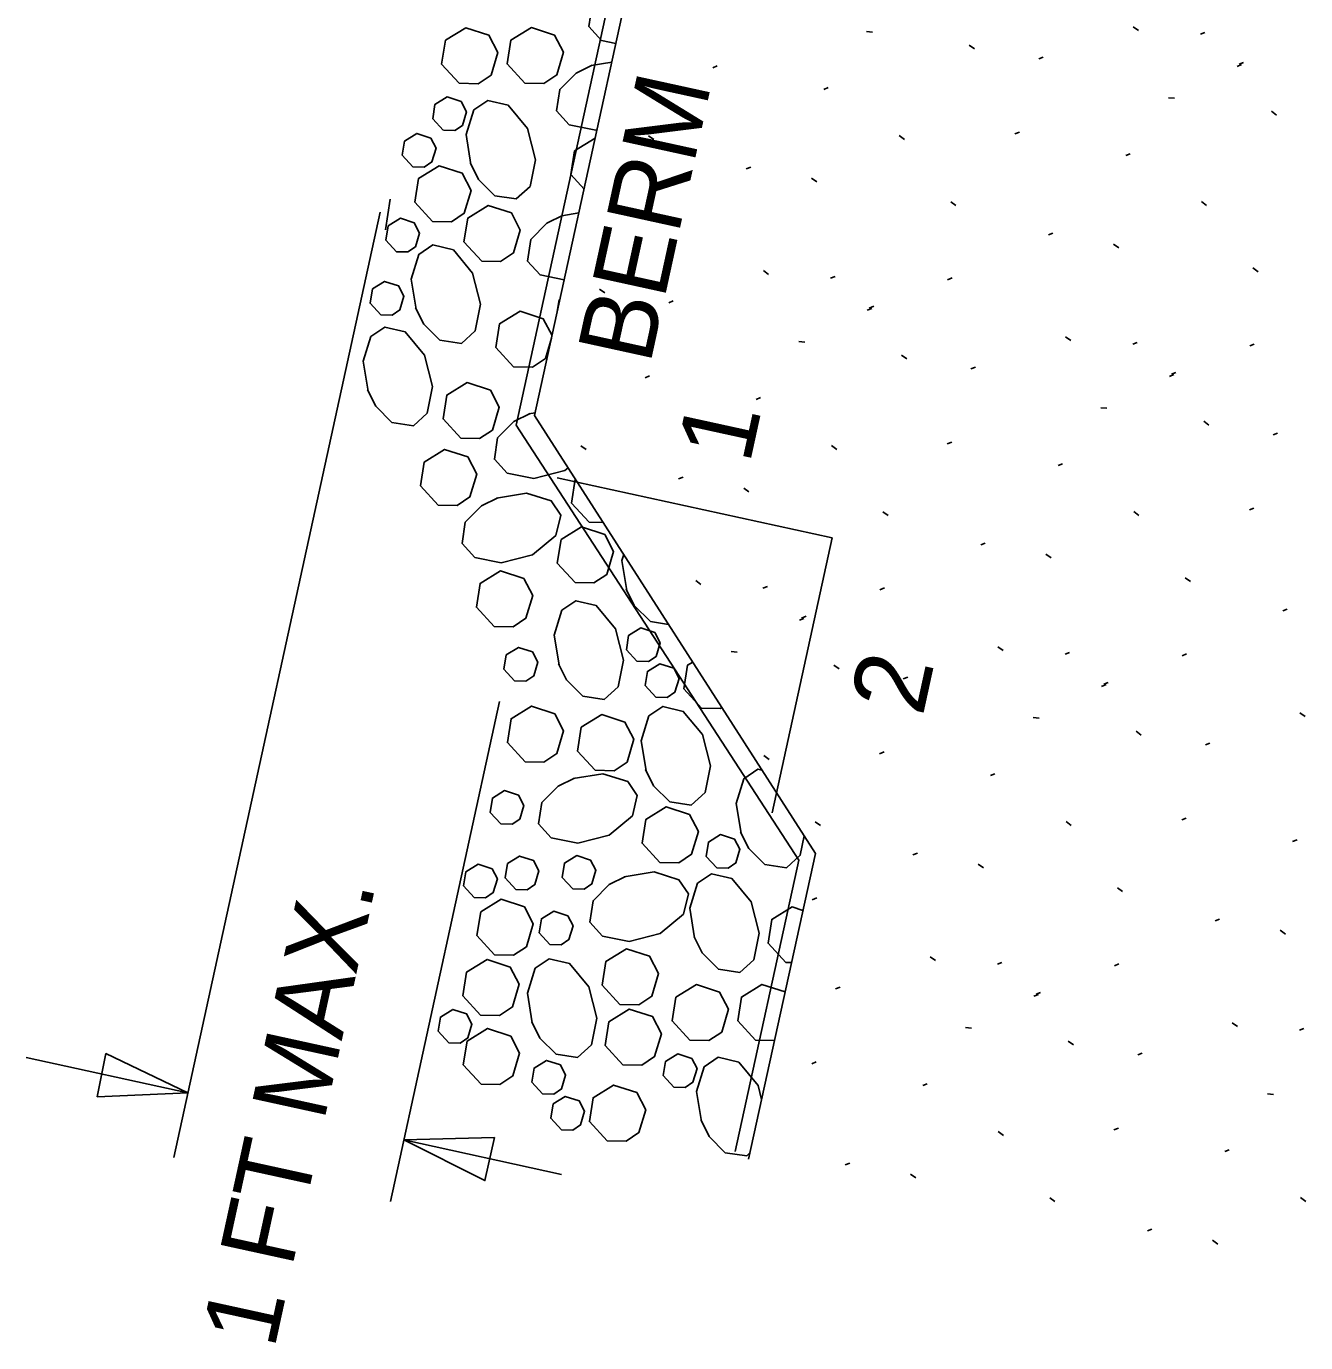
# Model space of a CAD drawing. Extents: x 2126110 to 2128246, y 1804858 to 1811658.
# Drawn here: x 2126703.9 to 2126789.7, y 1806267.7 to 1806355.9 of the extents above; entities that cross this region are included whole.
import ezdxf

# ---------------------------------------------------------------- set-up
doc = ezdxf.new("R2010")
doc.units = 0
doc.layers.add('1', color=7, linetype='Continuous')

msp = doc.modelspace()

# ---------------------------------------------------------------- linework, layer by layer
at = {"layer": '1'}
for p, q in [((2126736.789, 1806329.16), (2126742.894, 1806357.097)), ((2126743.847, 1806356.496), (2126738.017, 1806329.817)), ((2126760.279, 1806355.54), (2126760.679, 1806355.499)), ((2126778.519, 1806355.612), (2126778.167, 1806355.87)), ((2126782.676, 1806355.365), (2126782.974, 1806355.481)), ((2126767.524, 1806354.378), (2126767.172, 1806354.636)), ((2126771.826, 1806353.719), (2126772.124, 1806353.835)), ((2126741.803, 1806353.264), (2126743.191, 1806353.491)), ((2126749.974, 1806353.122), (2126750.272, 1806353.239)), ((2126785.13, 1806353.212), (2126785.429, 1806353.329)), ((2126785.267, 1806353.364), (2126785.566, 1806353.481)), ((2126757.41, 1806351.668), (2126757.708, 1806351.785)), ((2126780.541, 1806351.113), (2126780.941, 1806351.071)), ((2126787.787, 1806349.95), (2126787.434, 1806350.209)), ((2126746.013, 1806348.307), (2126745.66, 1806348.566)), ((2126762.83, 1806348.313), (2126762.477, 1806348.572)), ((2126770.236, 1806348.695), (2126770.534, 1806348.811)), ((2126777.673, 1806347.24), (2126777.971, 1806347.357)), ((2126752.213, 1806346.348), (2126752.511, 1806346.465)), ((2126756.936, 1806345.466), (2126756.583, 1806345.724)), ((2126728.01, 1806342.266), (2126728.334, 1806344.304)), ((2126766.275, 1806343.879), (2126765.923, 1806344.138)), ((2126783.092, 1806343.886), (2126782.74, 1806344.144)), ((2126727.665, 1806343.437), (2126713.821, 1806280.085)), ((2126739.853, 1806343.199), (2126740.982, 1806343.384)), ((2126745.459, 1806343.341), (2126745.757, 1806343.457)), ((2126772.475, 1806341.92), (2126772.774, 1806342.037)), ((2126777.198, 1806341.038), (2126776.846, 1806341.297)), ((2126753.716, 1806339.261), (2126753.364, 1806339.52)), ((2126786.538, 1806339.451), (2126786.185, 1806339.71)), ((2126757.873, 1806339.014), (2126758.171, 1806339.131)), ((2126765.721, 1806338.913), (2126766.019, 1806339.03)), ((2126742.721, 1806338.027), (2126742.369, 1806338.286)), ((2126747.023, 1806337.368), (2126747.321, 1806337.485)), ((2126760.327, 1806336.861), (2126760.626, 1806336.978)), ((2126760.464, 1806337.013), (2126760.763, 1806337.13)), ((2126773.979, 1806334.833), (2126773.627, 1806335.092)), ((2126755.738, 1806334.762), (2126756.138, 1806334.72)), ((2126778.135, 1806334.586), (2126778.434, 1806334.703)), ((2126785.984, 1806334.485), (2126786.282, 1806334.602)), ((2126762.984, 1806333.599), (2126762.631, 1806333.858)), ((2126745.433, 1806332.344), (2126745.731, 1806332.461)), ((2126767.285, 1806332.94), (2126767.583, 1806333.057)), ((2126780.59, 1806332.434), (2126780.888, 1806332.55)), ((2126780.727, 1806332.586), (2126781.025, 1806332.702)), ((2126752.87, 1806330.89), (2126753.168, 1806331.006)), ((2126737.637, 1806329.913), (2126738.053, 1806329.981)), ((2126738.017, 1806329.817), (2126756.848, 1806300.456)), ((2126776.001, 1806330.334), (2126776.401, 1806330.292)), ((2126755.732, 1806300.013), (2126736.789, 1806329.16)), ((2126783.246, 1806329.171), (2126782.894, 1806329.43)), ((2126765.696, 1806327.916), (2126765.994, 1806328.033)), ((2126787.548, 1806328.512), (2126787.846, 1806328.629)), ((2126741.472, 1806327.528), (2126741.12, 1806327.787)), ((2126758.289, 1806327.535), (2126757.937, 1806327.794)), ((2126773.132, 1806326.462), (2126773.431, 1806326.579)), ((2126739.525, 1806325.638), (2126757.976, 1806321.606)), ((2126747.672, 1806325.57), (2126747.971, 1806325.686)), ((2126752.395, 1806324.687), (2126752.043, 1806324.946)), ((2126785.958, 1806323.489), (2126786.257, 1806323.605)), ((2126761.735, 1806323.101), (2126761.382, 1806323.36)), ((2126778.552, 1806323.107), (2126778.2, 1806323.366)), ((2126742.626, 1806322.631), (2126741.674, 1806322.653)), ((2126757.976, 1806321.606), (2126753.947, 1806303.17)), ((2126767.935, 1806321.142), (2126768.233, 1806321.259)), ((2126772.658, 1806320.259), (2126772.305, 1806320.518)), ((2126749.176, 1806318.482), (2126748.823, 1806318.741)), ((2126753.332, 1806318.236), (2126753.631, 1806318.352)), ((2126781.997, 1806318.673), (2126781.645, 1806318.932)), ((2126761.181, 1806318.135), (2126761.479, 1806318.251)), ((2126788.197, 1806316.714), (2126788.496, 1806316.831)), ((2126755.787, 1806316.083), (2126756.085, 1806316.2)), ((2126755.924, 1806316.235), (2126756.222, 1806316.352)), ((2126751.198, 1806313.984), (2126751.598, 1806313.942)), ((2126769.439, 1806314.055), (2126769.086, 1806314.314)), ((2126773.595, 1806313.808), (2126773.893, 1806313.925)), ((2126758.443, 1806312.821), (2126758.091, 1806313.08)), ((2126781.443, 1806313.707), (2126781.742, 1806313.824)), ((2126762.745, 1806312.162), (2126763.043, 1806312.278)), ((2126776.05, 1806311.655), (2126776.348, 1806311.772)), ((2126776.186, 1806311.807), (2126776.485, 1806311.924)), ((2126735.667, 1806310.641), (2126728.343, 1806277.125)), ((2126771.46, 1806309.556), (2126771.86, 1806309.514)), ((2126789.701, 1806309.627), (2126789.349, 1806309.886)), ((2126778.706, 1806308.393), (2126778.353, 1806308.652)), ((2126783.007, 1806307.734), (2126783.306, 1806307.851)), ((2126753.749, 1806306.757), (2126753.396, 1806307.015)), ((2126761.155, 1806307.138), (2126761.454, 1806307.255)), ((2126768.592, 1806305.684), (2126768.89, 1806305.8)), ((2126757.194, 1806302.322), (2126756.842, 1806302.581)), ((2126774.012, 1806302.329), (2126773.659, 1806302.588)), ((2126781.418, 1806302.71), (2126781.716, 1806302.827)), ((2126788.854, 1806301.256), (2126789.153, 1806301.372)), ((2126751.464, 1806280.484), (2126755.732, 1806300.013)), ((2126752.372, 1806279.973), (2126756.848, 1806300.456)), ((2126763.394, 1806300.364), (2126763.693, 1806300.48)), ((2126768.117, 1806299.481), (2126767.765, 1806299.74)), ((2126777.457, 1806297.895), (2126777.104, 1806298.153)), ((2126756.64, 1806297.356), (2126756.938, 1806297.473)), ((2126783.657, 1806295.936), (2126783.955, 1806296.052)), ((2126788.38, 1806295.053), (2126788.027, 1806295.312)), ((2126755.249, 1806293.136), (2126754.861, 1806293.145)), ((2126764.898, 1806293.276), (2126764.546, 1806293.535)), ((2126769.054, 1806293.03), (2126769.353, 1806293.146)), ((2126776.903, 1806292.929), (2126777.201, 1806293.045)), ((2126758.204, 1806291.383), (2126758.503, 1806291.5)), ((2126771.509, 1806290.877), (2126771.807, 1806290.993)), ((2126771.646, 1806291.029), (2126771.944, 1806291.145)), ((2126766.92, 1806288.777), (2126767.32, 1806288.736)), ((2126785.161, 1806288.849), (2126784.808, 1806289.107)), ((2126789.317, 1806288.602), (2126789.615, 1806288.718)), ((2126774.165, 1806287.615), (2126773.813, 1806287.873)), ((2126703.927, 1806286.786), (2126714.768, 1806284.417)), ((2126778.467, 1806286.956), (2126778.765, 1806287.072)), ((2126756.615, 1806286.359), (2126756.913, 1806286.476)), ((2126764.051, 1806284.905), (2126764.35, 1806285.022)), ((2126787.183, 1806284.35), (2126787.582, 1806284.308)), ((2126729.246, 1806281.254), (2126739.819, 1806278.943)), ((2126769.471, 1806281.55), (2126769.119, 1806281.809)), ((2126776.877, 1806281.932), (2126777.176, 1806282.048)), ((2126784.314, 1806280.477), (2126784.612, 1806280.594)), ((2126758.854, 1806279.585), (2126759.152, 1806279.702)), ((2126763.577, 1806278.703), (2126763.224, 1806278.961)), ((2126772.916, 1806277.116), (2126772.564, 1806277.375)), ((2126789.734, 1806277.123), (2126789.381, 1806277.382)), ((2126779.117, 1806275.157), (2126779.415, 1806275.274)), ((2126783.839, 1806274.275), (2126783.487, 1806274.534))]:
    msp.add_line(p, q, dxfattribs=at)
for points in [[(2126743.466, 1806354.752), (2126742.507, 1806354.944), (2126741.661, 1806355.875), (2126741.876, 1806357.312), (2126742.965, 1806358.402), (2126744.058, 1806358.941)], [(2126732.965, 1806352.076), (2126731.778, 1806353.367), (2126732.033, 1806354.96), (2126733.405, 1806355.806), (2126734.959, 1806355.3), (2126735.555, 1806354.152), (2126735.103, 1806352.624), (2126734.235, 1806352.047), (2126732.965, 1806352.077)], [(2126737.363, 1806352.086), (2126736.176, 1806353.377), (2126736.431, 1806354.97), (2126737.803, 1806355.816), (2126739.357, 1806355.31), (2126739.953, 1806354.162), (2126739.501, 1806352.634), (2126738.633, 1806352.058), (2126737.363, 1806352.087)], [(2126742.201, 1806348.961), (2126742.122, 1806348.941), (2126740.337, 1806349.298), (2126739.491, 1806350.229), (2126739.706, 1806351.666), (2126740.795, 1806352.756), (2126741.887, 1806353.295)], [(2126731.896, 1806348.927), (2126731.184, 1806349.702), (2126731.336, 1806350.657), (2126732.161, 1806351.165), (2126733.092, 1806350.862), (2126733.45, 1806350.173), (2126733.179, 1806349.255), (2126732.658, 1806348.91), (2126731.897, 1806348.927)], [(2126733.748, 1806346.634), (2126733.42, 1806348.637), (2126733.936, 1806350.298), (2126734.877, 1806350.935), (2126736.245, 1806350.609), (2126737.539, 1806349.047), (2126738.07, 1806346.953), (2126737.713, 1806345.168), (2126736.783, 1806344.322), (2126735.345, 1806344.537), (2126734.256, 1806345.626), (2126733.717, 1806346.719)], [(2126729.851, 1806346.475), (2126729.14, 1806347.25), (2126729.292, 1806348.206), (2126730.116, 1806348.713), (2126731.048, 1806348.41), (2126731.406, 1806347.722), (2126731.134, 1806346.804), (2126730.614, 1806346.458), (2126729.852, 1806346.476)], [(2126741.333, 1806344.992), (2126740.448, 1806345.955), (2126740.702, 1806347.548), (2126742.075, 1806348.394), (2126742.077, 1806348.394)], [(2126731.166, 1806342.823), (2126729.98, 1806344.115), (2126730.233, 1806345.707), (2126731.607, 1806346.553), (2126733.16, 1806346.048), (2126733.756, 1806344.9), (2126733.304, 1806343.371), (2126732.436, 1806342.795), (2126731.166, 1806342.824)], [(2126734.469, 1806340.159), (2126733.282, 1806341.451), (2126733.536, 1806343.043), (2126734.909, 1806343.889), (2126736.463, 1806343.384), (2126737.059, 1806342.236), (2126736.607, 1806340.707), (2126735.738, 1806340.131), (2126734.469, 1806340.16)], [(2126728.749, 1806340.789), (2126728.037, 1806341.563), (2126728.189, 1806342.519), (2126729.014, 1806343.027), (2126729.945, 1806342.723), (2126730.303, 1806342.035), (2126730.032, 1806341.117), (2126729.511, 1806340.772), (2126728.75, 1806340.789)], [(2126740.004, 1806338.91), (2126738.387, 1806339.234), (2126737.542, 1806340.164), (2126737.757, 1806341.602), (2126738.846, 1806342.691), (2126739.938, 1806343.23)], [(2126730.07, 1806336.947), (2126729.742, 1806338.95), (2126730.258, 1806340.611), (2126731.199, 1806341.248), (2126732.567, 1806340.923), (2126733.862, 1806339.36), (2126734.393, 1806337.267), (2126734.035, 1806335.481), (2126733.105, 1806334.636), (2126731.668, 1806334.85), (2126730.578, 1806335.94), (2126730.039, 1806337.032)], [(2126727.696, 1806336.562), (2126726.984, 1806337.337), (2126727.136, 1806338.293), (2126727.96, 1806338.8), (2126728.892, 1806338.497), (2126729.25, 1806337.808), (2126728.979, 1806336.89), (2126728.457, 1806336.545), (2126727.696, 1806336.563)], [(2126739.511, 1806336.651), (2126739.656, 1806337.562), (2126739.718, 1806337.6)], [(2126736.604, 1806333.074), (2126735.418, 1806334.365), (2126735.672, 1806335.957), (2126737.045, 1806336.803), (2126738.599, 1806336.298), (2126739.186, 1806335.166)], [(2126726.85, 1806331.439), (2126726.522, 1806333.441), (2126727.038, 1806335.103), (2126727.979, 1806335.74), (2126729.347, 1806335.414), (2126730.642, 1806333.852), (2126731.173, 1806331.759), (2126730.815, 1806329.973), (2126729.885, 1806329.128), (2126728.448, 1806329.342), (2126727.358, 1806330.432), (2126726.819, 1806331.524)], [(2126739.149, 1806334.996), (2126738.743, 1806333.621), (2126737.874, 1806333.046), (2126736.605, 1806333.074)], [(2126733.061, 1806328.289), (2126731.876, 1806329.58), (2126732.129, 1806331.173), (2126733.502, 1806332.018), (2126735.056, 1806331.513), (2126735.652, 1806330.364), (2126735.2, 1806328.836), (2126734.332, 1806328.261), (2126733.062, 1806328.289)], [(2126740.271, 1806326.304), (2126740.05, 1806326.121), (2126737.956, 1806325.591), (2126736.171, 1806325.948), (2126735.325, 1806326.878), (2126735.54, 1806328.315), (2126736.629, 1806329.405), (2126737.722, 1806329.944)], [(2126731.544, 1806323.806), (2126730.357, 1806325.097), (2126730.612, 1806326.689), (2126731.984, 1806327.536), (2126733.538, 1806327.03), (2126734.134, 1806325.882), (2126733.683, 1806324.353), (2126732.814, 1806323.778), (2126731.544, 1806323.807)], [(2126741.674, 1806322.652), (2126740.487, 1806323.943), (2126740.741, 1806325.536), (2126740.757, 1806325.546)], [(2126735.467, 1806324.268), (2126737.469, 1806324.596), (2126739.131, 1806324.079), (2126739.768, 1806323.138), (2126739.442, 1806321.77), (2126737.88, 1806320.476), (2126735.786, 1806319.945), (2126734.001, 1806320.302), (2126733.155, 1806321.232), (2126733.37, 1806322.67), (2126734.459, 1806323.76), (2126735.551, 1806324.299)], [(2126740.728, 1806318.613), (2126739.542, 1806319.904), (2126739.796, 1806321.496), (2126741.169, 1806322.342), (2126742.722, 1806321.836), (2126743.318, 1806320.688), (2126742.867, 1806319.16), (2126741.999, 1806318.584), (2126740.729, 1806318.613)], [(2126744.197, 1806318.087), (2126743.869, 1806320.09), (2126743.996, 1806320.496)], [(2126735.298, 1806315.668), (2126734.112, 1806316.959), (2126734.366, 1806318.552), (2126735.739, 1806319.398), (2126737.293, 1806318.893), (2126737.889, 1806317.745), (2126737.437, 1806316.216), (2126736.569, 1806315.64), (2126735.298, 1806315.669)], [(2126747.001, 1806315.81), (2126745.795, 1806315.991), (2126744.705, 1806317.079), (2126744.167, 1806318.172)], [(2126739.656, 1806313.089), (2126739.328, 1806315.092), (2126739.844, 1806316.753), (2126740.785, 1806317.39), (2126742.153, 1806317.064), (2126743.447, 1806315.502), (2126743.978, 1806313.408), (2126743.621, 1806311.623), (2126742.691, 1806310.777), (2126741.253, 1806310.992), (2126740.164, 1806312.081), (2126739.625, 1806313.173)], [(2126744.883, 1806313.336), (2126744.171, 1806314.112), (2126744.324, 1806315.067), (2126745.147, 1806315.574), (2126746.08, 1806315.271), (2126746.437, 1806314.582), (2126746.166, 1806313.665), (2126745.646, 1806313.32), (2126744.883, 1806313.337)], [(2126736.674, 1806312.03), (2126735.962, 1806312.805), (2126736.115, 1806313.761), (2126736.939, 1806314.268), (2126737.87, 1806313.965), (2126738.228, 1806313.276), (2126737.957, 1806312.359), (2126737.436, 1806312.013), (2126736.674, 1806312.03)], [(2126746.148, 1806310.93), (2126745.437, 1806311.705), (2126745.589, 1806312.661), (2126746.413, 1806313.168), (2126747.345, 1806312.865), (2126747.703, 1806312.176), (2126747.432, 1806311.259), (2126746.911, 1806310.913), (2126746.149, 1806310.931)], [(2126749.214, 1806310.191), (2126748.028, 1806311.483), (2126748.282, 1806313.076), (2126748.621, 1806313.285)], [(2126737.375, 1806306.597), (2126736.189, 1806307.889), (2126736.443, 1806309.481), (2126737.815, 1806310.327), (2126739.37, 1806309.821), (2126739.966, 1806308.673), (2126739.514, 1806307.145), (2126738.645, 1806306.569), (2126737.376, 1806306.598)], [(2126742.082, 1806306.028), (2126740.895, 1806307.319), (2126741.15, 1806308.912), (2126742.522, 1806309.758), (2126744.076, 1806309.252), (2126744.672, 1806308.104), (2126744.22, 1806306.575), (2126743.352, 1806305.999), (2126742.082, 1806306.028)], [(2126745.49, 1806306.004), (2126745.163, 1806308.007), (2126745.679, 1806309.668), (2126746.62, 1806310.305), (2126747.988, 1806309.979), (2126749.282, 1806308.417), (2126749.813, 1806306.324), (2126749.456, 1806304.538), (2126748.526, 1806303.693), (2126747.088, 1806303.907), (2126745.999, 1806304.997), (2126745.46, 1806306.089)], [(2126750.581, 1806310.228), (2126750.484, 1806310.163), (2126749.215, 1806310.193)], [(2126751.869, 1806301.803), (2126751.541, 1806303.805), (2126752.057, 1806305.467), (2126752.997, 1806306.104), (2126753.267, 1806306.04)], [(2126740.602, 1806305.473), (2126742.604, 1806305.802), (2126744.265, 1806305.285), (2126744.903, 1806304.345), (2126744.577, 1806302.976), (2126743.014, 1806301.682), (2126740.922, 1806301.151), (2126739.136, 1806301.509), (2126738.29, 1806302.439), (2126738.505, 1806303.877), (2126739.594, 1806304.966), (2126740.687, 1806305.505)], [(2126735.744, 1806302.432), (2126735.032, 1806303.206), (2126735.185, 1806304.163), (2126736.009, 1806304.67), (2126736.94, 1806304.366), (2126737.298, 1806303.678), (2126737.027, 1806302.76), (2126736.506, 1806302.414), (2126735.745, 1806302.432)], [(2126746.41, 1806299.851), (2126745.223, 1806301.142), (2126745.478, 1806302.735), (2126746.85, 1806303.581), (2126748.404, 1806303.075), (2126749, 1806301.927), (2126748.548, 1806300.398), (2126747.68, 1806299.823), (2126746.41, 1806299.852)], [(2126750.231, 1806299.486), (2126749.52, 1806300.261), (2126749.672, 1806301.217), (2126750.496, 1806301.724), (2126751.428, 1806301.421), (2126751.786, 1806300.732), (2126751.515, 1806299.815), (2126750.993, 1806299.469), (2126750.232, 1806299.487)], [(2126756.093, 1806301.633), (2126755.833, 1806300.337), (2126754.903, 1806299.492), (2126753.466, 1806299.706), (2126752.376, 1806300.795), (2126751.837, 1806301.888)], [(2126736.75, 1806298.044), (2126736.038, 1806298.818), (2126736.19, 1806299.775), (2126737.014, 1806300.282), (2126737.946, 1806299.978), (2126738.304, 1806299.29), (2126738.033, 1806298.372), (2126737.512, 1806298.026), (2126736.75, 1806298.044)], [(2126740.581, 1806298.077), (2126739.87, 1806298.852), (2126740.022, 1806299.808), (2126740.846, 1806300.316), (2126741.777, 1806300.012), (2126742.135, 1806299.324), (2126741.864, 1806298.407), (2126741.343, 1806298.061), (2126740.582, 1806298.078)], [(2126733.966, 1806297.5), (2126733.254, 1806298.274), (2126733.406, 1806299.23), (2126734.23, 1806299.737), (2126735.162, 1806299.434), (2126735.52, 1806298.746), (2126735.249, 1806297.828), (2126734.728, 1806297.482), (2126733.966, 1806297.5)], [(2126744.033, 1806298.883), (2126746.035, 1806299.212), (2126747.696, 1806298.695), (2126748.334, 1806297.754), (2126748.008, 1806296.386), (2126746.445, 1806295.092), (2126744.352, 1806294.561), (2126742.567, 1806294.918), (2126741.72, 1806295.849), (2126741.936, 1806297.286), (2126743.024, 1806298.376), (2126744.117, 1806298.915)], [(2126748.751, 1806294.791), (2126748.423, 1806296.794), (2126748.939, 1806298.455), (2126749.88, 1806299.092), (2126751.248, 1806298.767), (2126752.543, 1806297.205), (2126753.074, 1806295.111), (2126752.716, 1806293.325), (2126751.786, 1806292.48), (2126750.349, 1806292.694), (2126749.259, 1806293.784), (2126748.72, 1806294.876)], [(2126735.338, 1806293.656), (2126734.151, 1806294.947), (2126734.405, 1806296.54), (2126735.778, 1806297.386), (2126737.332, 1806296.88), (2126737.928, 1806295.731), (2126737.476, 1806294.204), (2126736.608, 1806293.628), (2126735.338, 1806293.657)], [(2126739.04, 1806294.348), (2126738.328, 1806295.123), (2126738.48, 1806296.079), (2126739.304, 1806296.586), (2126740.237, 1806296.283), (2126740.595, 1806295.594), (2126740.323, 1806294.677), (2126739.802, 1806294.332), (2126739.041, 1806294.349)], [(2126754.86, 1806293.145), (2126753.674, 1806294.436), (2126753.928, 1806296.028), (2126755.3, 1806296.874), (2126756.015, 1806296.641)], [(2126743.738, 1806290.336), (2126742.551, 1806291.627), (2126742.805, 1806293.22), (2126744.178, 1806294.066), (2126745.732, 1806293.561), (2126746.328, 1806292.412), (2126745.876, 1806290.884), (2126745.008, 1806290.308), (2126743.738, 1806290.337)], [(2126734.392, 1806289.616), (2126733.206, 1806290.907), (2126733.46, 1806292.5), (2126734.832, 1806293.346), (2126736.386, 1806292.84), (2126736.982, 1806291.692), (2126736.531, 1806290.164), (2126735.663, 1806289.588), (2126734.393, 1806289.617)], [(2126737.861, 1806289.091), (2126737.533, 1806291.094), (2126738.05, 1806292.755), (2126738.991, 1806293.393), (2126740.359, 1806293.067), (2126741.653, 1806291.504), (2126742.184, 1806289.411), (2126741.827, 1806287.626), (2126740.896, 1806286.779), (2126739.459, 1806286.995), (2126738.369, 1806288.083), (2126737.83, 1806289.176)], [(2126748.427, 1806287.936), (2126747.24, 1806289.227), (2126747.495, 1806290.82), (2126748.867, 1806291.665), (2126750.421, 1806291.16), (2126751.017, 1806290.012), (2126750.566, 1806288.483), (2126749.697, 1806287.907), (2126748.427, 1806287.937)], [(2126752.825, 1806287.946), (2126751.638, 1806289.237), (2126751.893, 1806290.83), (2126753.265, 1806291.675), (2126754.819, 1806291.17), (2126754.819, 1806291.17)], [(2126732.264, 1806287.759), (2126731.552, 1806288.534), (2126731.704, 1806289.489), (2126732.528, 1806289.997), (2126733.461, 1806289.694), (2126733.818, 1806289.004), (2126733.547, 1806288.087), (2126733.026, 1806287.742), (2126732.264, 1806287.76)], [(2126743.93, 1806286.291), (2126742.745, 1806287.582), (2126742.998, 1806289.175), (2126744.371, 1806290.021), (2126745.925, 1806289.515), (2126746.521, 1806288.367), (2126746.069, 1806286.838), (2126745.201, 1806286.263), (2126743.931, 1806286.292)], [(2126734.423, 1806284.995), (2126733.236, 1806286.286), (2126733.491, 1806287.878), (2126734.863, 1806288.724), (2126736.417, 1806288.218), (2126737.013, 1806287.07), (2126736.562, 1806285.542), (2126735.693, 1806284.967), (2126734.424, 1806284.995)], [(2126754.111, 1806287.928), (2126754.095, 1806287.918), (2126752.825, 1806287.947)], [(2126738.547, 1806284.34), (2126737.835, 1806285.115), (2126737.988, 1806286.071), (2126738.811, 1806286.578), (2126739.744, 1806286.275), (2126740.101, 1806285.586), (2126739.83, 1806284.669), (2126739.309, 1806284.323), (2126738.547, 1806284.341)], [(2126747.358, 1806284.786), (2126746.647, 1806285.561), (2126746.799, 1806286.517), (2126747.623, 1806287.025), (2126748.554, 1806286.721), (2126748.912, 1806286.033), (2126748.641, 1806285.115), (2126748.12, 1806284.769), (2126747.359, 1806284.787)], [(2126749.21, 1806282.494), (2126748.882, 1806284.496), (2126749.399, 1806286.157), (2126750.339, 1806286.795), (2126751.708, 1806286.469), (2126753.001, 1806284.907), (2126753.243, 1806283.955)], [(2126742.877, 1806281.195), (2126741.692, 1806282.487), (2126741.945, 1806284.08), (2126743.318, 1806284.925), (2126744.873, 1806284.42), (2126745.468, 1806283.271), (2126745.016, 1806281.743), (2126744.148, 1806281.167), (2126742.878, 1806281.197)], [(2126739.812, 1806281.934), (2126739.1, 1806282.709), (2126739.253, 1806283.665), (2126740.076, 1806284.172), (2126741.009, 1806283.869), (2126741.367, 1806283.18), (2126741.095, 1806282.263), (2126740.575, 1806281.917), (2126739.812, 1806281.935)], [(2126752.461, 1806280.378), (2126752.245, 1806280.182), (2126750.807, 1806280.397), (2126749.718, 1806281.486), (2126749.179, 1806282.579)]]:
    msp.add_lwpolyline(points, dxfattribs=at)
for points in [[(2126708.686, 1806284.139), (2126714.768, 1806284.417), (2126709.271, 1806287.034)], [(2126735.332, 1806281.404), (2126729.246, 1806281.254), (2126734.686, 1806278.522)]]:
    msp.add_lwpolyline(points, close=True, dxfattribs=at)

# ---------------------------------------------------------------- texts
for s, p in [('BERM', (2126745.753, 1806333.145)), ('1', (2126752.435, 1806326.478)), ('2', (2126764.039, 1806309.569)), ('1 FT MAX.', (2126720.552, 1806267.164))]:
    msp.add_text(s, height=5, rotation=77.67359, dxfattribs=at).set_placement(p)

doc.saveas('drawing.dxf')
